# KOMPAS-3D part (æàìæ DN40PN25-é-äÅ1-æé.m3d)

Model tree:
1. Объединить компоненты:1  (labels: СЕНС DN40PN25-В-ДП1)
2. Эскиз:1
3. Операция выдавливания:1
     Расстояние 1 = 14
4. Фаска:1
     Угол = 45; Длина 1 = 2; Длина 2 = 2

Referenced files in D:\Савин\!СЕНСОР\3D для заказчика\!Новый перечень\СЕНС\5. СЕНС-В-ДП\DN40\: СЕНС DN40PN25-В-ДП1.a3d
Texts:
  СЕНС DN40PN25-В-ДП1-СВ
  ООО НПП Сенсор
  СЕНС DN40PN25-В-ДП1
